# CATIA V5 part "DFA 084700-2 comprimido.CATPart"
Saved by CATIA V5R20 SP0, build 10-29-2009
Part number: DFA 084700-2 comprimido
Revision: ANY
Definition: UNKNOWN
Nomenclature: DFA 084700-2 comprimido
Source: Unknown
Bounding box of the stored display mesh (mm): x -2.45 to 2.45, y 0 to 4.72, z -2.45 to 2.45
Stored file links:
  C:\Users\Utente\Desktop\IO LAVORO\3D X SITO CF\CUMSA\3D files FA\FA 084705-21\DFA 084700-2 comprimido.CATPart
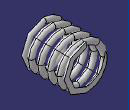
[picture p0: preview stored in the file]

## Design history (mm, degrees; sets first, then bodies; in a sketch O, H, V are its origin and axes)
Body1 "Cortar-Extruir1" (main body)
  Solid1: solid without history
